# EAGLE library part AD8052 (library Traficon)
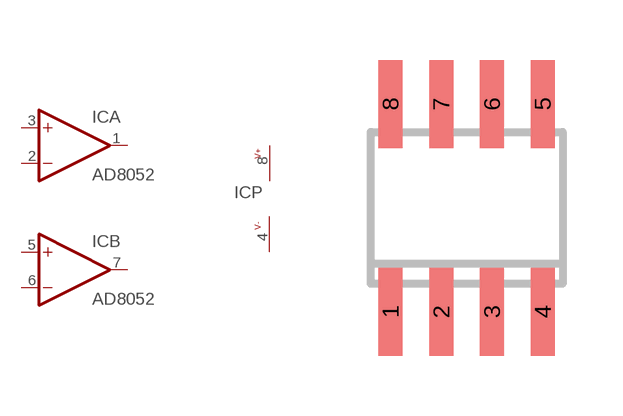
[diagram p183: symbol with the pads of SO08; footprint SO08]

Designator prefix IC; gates A=OPAMP B=OPAMP P=PWR+-

## AD8052  [SO08]
1  A:OUT  out
2  A:-IN  in
3  A:+IN  in
4  P:V-  pas
5  B:+IN  in
6  B:-IN  in
7  B:OUT  out
8  P:V+  pas

## Footprint SO08 (pad centres in mm)
Small Outline Package
smd 0.6 x 2.2: 1 -1.905,-2.6; 2 -0.635,-2.6; 3 0.635,-2.6; 4 1.905,-2.6; 5 1.905,2.6; 6 0.635,2.6; 7 -0.635,2.6; 8 -1.905,2.6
